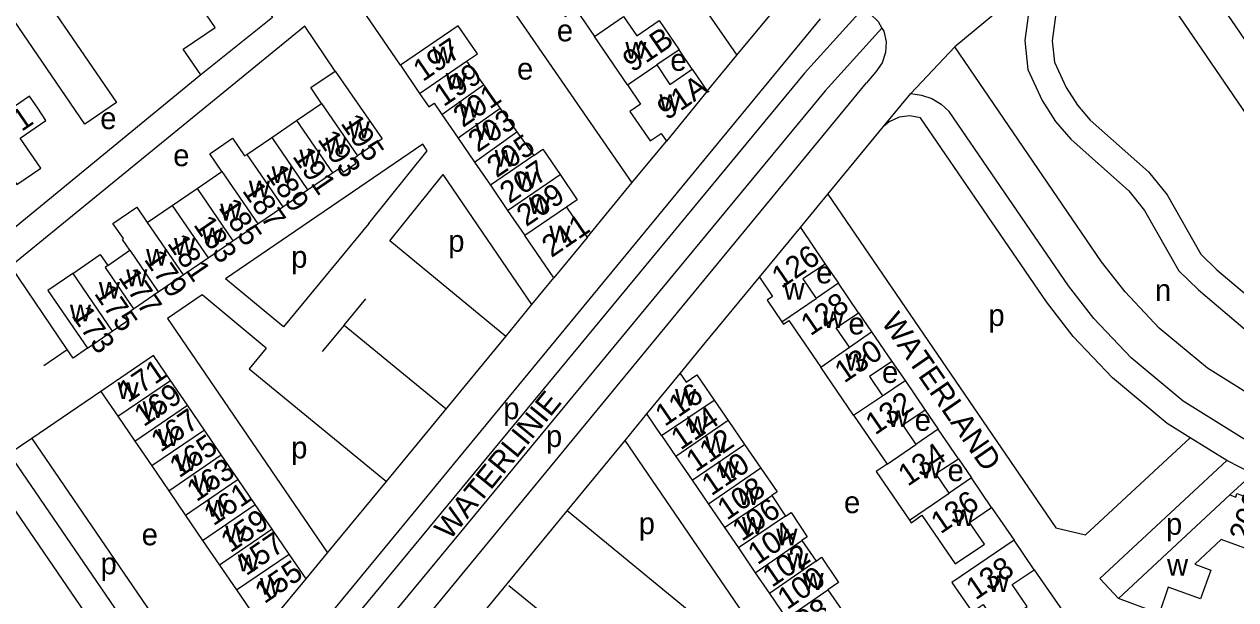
# Model space of a CAD drawing. Extents: x 154320 to 156262, y 382651 to 384180.
# Drawn here: x 155553.7 to 155775.5, y 383033.1 to 383138.5 of the extents above; entities that cross this region are included whole.
import ezdxf

# ---------------------------------------------------------------- set-up
doc = ezdxf.new("R2010")
doc.units = 0
for name, color, linetype in [('BLT_Basislijn', 7, 'Continuous'), ('BLT_Bebouwing', 7, 'Continuous'), ('BLT_Centroide', 7, 'Continuous'), ('BLT_Huisnummer', 7, 'Continuous'), ('BLT_Onderverdeling_panden', 7, 'Continuous'), ('BLT_Straatnaam', 7, 'Continuous'), ('BLT_Vlakafsluiter', 7, 'Continuous')]:
    doc.layers.add(name, color=color, linetype=linetype)

msp = doc.modelspace()

# ---------------------------------------------------------------- linework, layer by layer
at = {"layer": 'BLT_Basislijn'}
for p, q in [((155533.34, 383178.68), (155570.55, 383124.16)), ((155653.33, 383177.6), (155684.15, 383132.85)), ((155630.7, 383159.12), (155664.96, 383109.46)), ((155684.15, 383132.85), (155696.27, 383147.42)), ((155622.57, 383130.99), (155613.26, 383144.61)), ((155605.07, 383138.19), (155551.22, 383094.22)), ((155577.92, 382991.91), (155699.45, 383139.48)), ((155610.61, 383129.95), (155605.07, 383138.19)), ((155675.96, 383130.29), (155673.57, 383133.84)), ((155678.75, 383126.24), (155684.15, 383132.85)), ((155585.98, 383129.24), (155548.41, 383098.38)), ((155588.6, 382982.86), (155707.89, 383127.77)), ((155711.02, 383119.77), (155716, 383125.82)), ((155700.83, 383107.41), (155711.02, 383119.77)), ((155616.74, 383102.04), (155627.46, 383115.34)), ((155664.96, 383109.46), (155671.25, 383117.08)), ((155620.6, 383098.86), (155630.4, 383111.02)), ((155656.74, 383099.48), (155664.96, 383109.46)), ((155695.79, 383101.32), (155700.83, 383107.41)), ((155561.54, 383078.94), (155551.22, 383094.22)), ((155700.34, 383094.6), (155702.75, 383091.1)), ((155601.14, 383083.08), (155590.52, 383091.89)), ((155646.64, 383087.18), (155650.63, 383092.05)), ((155678.13, 383079.84), (155688.29, 383092.17)), ((155597.96, 383079.22), (155586.22, 383088.95)), ((155612.27, 383083.41), (155616.2, 383088.26)), ((155641.86, 383081.35), (155646.64, 383087.18)), ((155706.44, 383085.68), (155708.85, 383082.17)), ((155612.27, 383083.41), (155608.25, 383078.59)), ((155612.27, 383083.41), (155630.93, 383068.07)), ((155619.98, 383054.78), (155641.86, 383081.35)), ((155673.79, 383074.57), (155678.13, 383079.84)), ((155712.55, 383076.75), (155714.96, 383073.26)), ((155567.7, 383071.29), (155555.06, 383062.66)), ((155663.69, 383062.31), (155667.69, 383067.17)), ((155718.63, 383067.85), (155721.03, 383064.34)), ((155555.06, 383062.66), (155550.93, 383059.84)), ((155555.06, 383062.66), (155587.44, 383015.29)), ((155653.07, 383049.4), (155663.69, 383062.31)), ((155691.94, 383020.97), (155663.69, 383062.31)), ((155773.87, 383058.61), (155767.16, 383062.8)), ((155550.93, 383059.84), (155584.13, 383011.26)), ((155545.57, 383058.83), (155580.83, 383007.24)), ((155724.74, 383058.92), (155727.12, 383055.43)), ((155774.44, 383052.32), (155778.65, 383056.19)), ((155609.23, 383041.74), (155619.98, 383054.78)), ((155631.15, 383022.79), (155653.07, 383049.4)), ((155730.81, 383050.02), (155734.93, 383044.04)), ((155605.27, 383036.94), (155609.23, 383041.74)), ((155738.6, 383038.61), (155743.96, 383030.84)), ((155642.42, 383035.73), (155661.52, 383020.19)), ((155750.64, 383037.04), (155754.04, 383033.38))]:
    msp.add_line(p, q, dxfattribs=at)
for points in [[(155564.78, 383120.21), (155519.64, 383186.24)], [(155754.67, 383155.35), (155781.59, 383115.97), (155786.38, 383110.5), (155792.35, 383105.37), (155799.06, 383101.19), (155805.08, 383098.89), (155853.42, 383081.31)], [(155765.85, 383152.28), (155787.53, 383120.57), (155791.67, 383115.84), (155796.8, 383111.44), (155801.33, 383108.62)], [(155741.32, 383147.65), (155743.08, 383144.14), (155741.93, 383135.48), (155742.34, 383131.59), (155744.48, 383126.93), (155746.56, 383123.69), (155748.88, 383120.95), (155759.56, 383111.48), (155762.98, 383107.25), (155769.13, 383096.43), (155772.05, 383093.56), (155780.98, 383086.01), (155786.93, 383082.35), (155790.66, 383081.54), (155799.19, 383082.02), (155803.24, 383081.5), (155808.51, 383079.32), (155812.25, 383076.51), (155815.09, 383073.7)], [(155737.15, 383144.82), (155734.45, 383142.87), (155731.5, 383140.57), (155724.08, 383134.36)], [(155737.15, 383144.82), (155737.92, 383143.28), (155736.89, 383135.55), (155737.46, 383130.24), (155740.09, 383124.52), (155742.53, 383120.71), (155745.3, 383117.45), (155755.93, 383108.02), (155758.83, 383104.43), (155765.13, 383093.35), (155768.68, 383089.86), (155778.04, 383081.95), (155785.04, 383077.64), (155790.27, 383076.51), (155799.01, 383077), (155801.94, 383076.62), (155806.02, 383074.94), (155808.98, 383072.72), (155811.69, 383070.03), (155812.04, 383067.38), (155811.6, 383064.12), (155810.66, 383061.59), (155808.19, 383058.28)], [(155707.05, 383141.17), (155696.56, 383129.57), (155576.82, 382984.73)], [(155707.05, 383141.17), (155708.61, 383140.37), (155710.05, 383138.99), (155710.74, 383137.8)], [(155710.74, 383137.8), (155700.35, 383126.3), (155580.3, 382981.1)], [(155710.74, 383137.8), (155711.05, 383137.25), (155711.52, 383135.31), (155711.4, 383133.31), (155710.75, 383131.42), (155709.59, 383129.8), (155707.89, 383127.77)], [(155808.19, 383058.28), (155793.79, 383063.51), (155781.76, 383068.42), (155770.32, 383075.56), (155761.52, 383082.89), (155755.26, 383089.5), (155750.96, 383095.03), (155724.08, 383134.36)], [(155570.55, 383124.16), (155564.78, 383120.21)], [(155716, 383125.82), (155717.98, 383125.54), (155719.87, 383124.89), (155721.59, 383123.87), (155723.07, 383122.55)], [(155805.3, 383051.35), (155791.1, 383056.52), (155778.33, 383061.72), (155765.92, 383069.47), (155756.38, 383077.4), (155749.56, 383084.61), (155744.9, 383090.61), (155723.07, 383122.55)], [(155717.81, 383121.38), (155715.84, 383121.76), (155713.86, 383121.51), (155712.05, 383120.66), (155711.02, 383119.77)], [(155767.16, 383062.8), (155762.98, 383065.41), (155752.95, 383073.75), (155745.76, 383081.35), (155740.86, 383087.66), (155717.81, 383121.38)], [(155627.46, 383115.34), (155626.65, 383116.53), (155590.52, 383091.89)], [(155646.64, 383087.18), (155630.4, 383111.02)], [(155700.83, 383107.41), (155742.55, 383046.3), (155748.01, 383045.04), (155767.16, 383062.8)], [(155616.74, 383102.04), (155601.14, 383083.08)], [(155641.86, 383081.35), (155620.6, 383098.86)], [(155586.22, 383088.95), (155579.92, 383084.66), (155609.23, 383041.74)], [(155557.28, 383076.03), (155561.54, 383078.94)], [(155565.23, 383079.17), (155562.6, 383077.39), (155561.54, 383078.94)], [(155597.96, 383079.22), (155594.85, 383075.43), (155619.98, 383054.78)], [(155778.65, 383056.19), (155773.87, 383058.61)], [(155678.17, 383028.75), (155653.07, 383049.4)]]:
    msp.add_lwpolyline(points, dxfattribs=at)
at = {"layer": 'BLT_Bebouwing'}
for p, q in [((155599.13, 383139.76), (155585.98, 383129.24)), ((155669.92, 383139.21), (155673.57, 383133.84)), ((155664.12, 383127.42), (155658.09, 383136.29)), ((155673.57, 383133.84), (155669.48, 383131.06)), ((155675.96, 383130.29), (155678.75, 383126.24)), ((155637.75, 383127.42), (155640.82, 383123.1)), ((155678.75, 383126.24), (155671.25, 383117.08)), ((155603.54, 383120.91), (155608.09, 383124.02)), ((155630.15, 383122), (155633.14, 383117.63)), ((155640.82, 383123.1), (155643.89, 383118.79)), ((155598.98, 383117.8), (155603.54, 383120.91)), ((155594.42, 383114.68), (155598.98, 383117.8)), ((155633.14, 383117.63), (155636.13, 383113.26)), ((155643.89, 383118.79), (155646.96, 383114.47)), ((155636.13, 383113.26), (155639.02, 383109.03)), ((155605.55, 383108.18), (155610.11, 383111.29)), ((155639.02, 383109.03), (155642.18, 383104.4)), ((155580.76, 383105.35), (155585.31, 383108.46)), ((155601, 383105.06), (155605.55, 383108.18)), ((155576.2, 383102.24), (155580.76, 383105.35)), ((155596.44, 383101.95), (155601, 383105.06)), ((155642.18, 383104.4), (155645.33, 383099.8)), ((155652.95, 383105), (155656.74, 383099.48)), ((155591.89, 383098.84), (155596.44, 383101.95)), ((155650.63, 383092.05), (155645.33, 383099.8)), ((155688.29, 383092.17), (155695.79, 383101.32)), ((155587.33, 383095.72), (155591.89, 383098.84)), ((155656.74, 383099.48), (155650.63, 383092.05)), ((155568.95, 383094.33), (155573.02, 383097.12)), ((155582.78, 383092.61), (155587.33, 383095.72)), ((155578.22, 383089.5), (155582.78, 383092.61)), ((155573.67, 383086.38), (155578.22, 383089.5)), ((155705.55, 383066.9), (155699.52, 383075.73)), ((155583.54, 383068.75), (155580.44, 383073.3)), ((155667.69, 383067.17), (155673.79, 383074.57)), ((155586.65, 383064.21), (155583.54, 383068.75)), ((155679.99, 383069.69), (155682.57, 383065.93)), ((155570.81, 383066.72), (155573.9, 383062.17)), ((155670.39, 383063.21), (155667.69, 383067.17)), ((155705.55, 383066.9), (155711.67, 383057.94)), ((155589.75, 383059.67), (155586.65, 383064.21)), ((155573.9, 383062.17), (155577.01, 383057.63)), ((155670.39, 383063.21), (155673.01, 383059.36)), ((155685.56, 383061.58), (155688.55, 383057.23)), ((155577.01, 383057.63), (155580.12, 383053.09)), ((155592.85, 383055.12), (155589.75, 383059.67)), ((155673.01, 383059.36), (155675.99, 383055)), ((155750.64, 383037.04), (155773.87, 383058.61)), ((155580.12, 383053.09), (155583.22, 383048.55)), ((155595.96, 383050.58), (155592.85, 383055.12)), ((155675.99, 383055), (155678.97, 383050.64)), ((155690.54, 383052.2), (155693.1, 383048.41)), ((155754.04, 383033.38), (155774.44, 383052.32)), ((155599.06, 383046.03), (155595.96, 383050.58)), ((155678.97, 383050.64), (155681.9, 383046.35)), ((155583.22, 383048.55), (155586.33, 383044)), ((155602.16, 383041.49), (155599.06, 383046.03)), ((155681.9, 383046.35), (155684.45, 383042.61)), ((155586.33, 383044), (155589.44, 383039.46)), ((155684.45, 383042.61), (155687.54, 383038.08)), ((155696.07, 383043.99), (155698.68, 383040.22)), ((155605.27, 383036.94), (155602.16, 383041.49)), ((155589.44, 383039.46), (155592.54, 383034.92)), ((155687.54, 383038.08), (155690.12, 383034.3)), ((155599.14, 383029.51), (155605.27, 383036.94)), ((155690.12, 383034.3), (155693.27, 383029.7)), ((155700.81, 383034.93), (155703.43, 383031.15)), ((155760.94, 383030.78), (155754.04, 383033.38))]:
    msp.add_line(p, q, dxfattribs=at)
for points in [[(155585.98, 383129.24), (155582.75, 383133.96), (155588.63, 383137.9), (155585.36, 383142.77), (155594.27, 383148.74), (155597.6, 383143.82), (155596.39, 383143), (155597.78, 383140.94), (155598.14, 383141.18), (155599.13, 383139.76)], [(155650.94, 383144.76), (155649.96, 383143.94), (155652.71, 383139.96), (155654.69, 383141.3), (155658.09, 383136.29)], [(155663.41, 383139.96), (155665.82, 383136.42), (155669.92, 383139.21)], [(155634.68, 383131.73), (155636.68, 383133.09), (155633.15, 383138.24), (155622.57, 383130.99)], [(155622.57, 383130.99), (155626.06, 383125.86)], [(155634.68, 383131.73), (155634.68, 383131.73), (155637.75, 383127.42)], [(155669.48, 383131.06), (155671.9, 383127.5), (155675.96, 383130.29)], [(155608.09, 383124.02), (155606.12, 383126.91), (155610.61, 383129.95)], [(155610.61, 383129.95), (155619.22, 383117.52), (155614.67, 383114.41)], [(155664.12, 383127.42), (155666.54, 383123.85), (155664.56, 383122.53), (155668.29, 383117.18), (155670.28, 383118.5), (155671.25, 383117.08)], [(155626.06, 383125.86), (155627.73, 383123.4), (155628.75, 383124.05), (155630.15, 383122)], [(155589.87, 383111.57), (155587.66, 383114.78), (155591.83, 383117.63), (155594.03, 383114.41), (155594.42, 383114.68)], [(155646.96, 383114.47), (155648.61, 383115.61), (155651.78, 383110.98)], [(155610.11, 383111.29), (155611.49, 383112.23), (155612.04, 383111.42), (155614.48, 383113.09), (155613.93, 383113.9), (155614.67, 383114.41)], [(155585.31, 383108.46), (155585.31, 383108.46), (155589.87, 383111.57)], [(155651.78, 383110.98), (155654.95, 383106.36), (155652.95, 383105)], [(155573.02, 383097.12), (155571.63, 383099.12), (155571.82, 383099.25), (155569.91, 383102.05), (155574.29, 383105.04), (155576.2, 383102.24)], [(155695.79, 383101.32), (155700.34, 383094.6)], [(155562.54, 383092.89), (155567.59, 383096.33), (155568.95, 383094.33)], [(155700.34, 383094.6), (155696.24, 383091.87), (155698.67, 383088.31)], [(155562.54, 383092.89), (155557.99, 383089.78), (155565.23, 383079.17)], [(155688.29, 383092.17), (155690.69, 383088.64), (155689.69, 383087.98), (155692.39, 383084.03)], [(155702.75, 383091.1), (155698.67, 383088.31)], [(155706.44, 383085.68), (155702.75, 383091.1)], [(155569.78, 383082.29), (155572.85, 383084.4), (155572.18, 383085.37), (155573.67, 383086.38)], [(155692.39, 383084.03), (155692.7, 383083.58), (155693.69, 383084.26), (155699.52, 383075.73)], [(155704.78, 383079.36), (155702.32, 383082.93), (155706.44, 383085.68)], [(155565.23, 383079.17), (155569.78, 383082.29)], [(155704.78, 383079.36), (155708.85, 383082.17)], [(155708.85, 383082.17), (155712.55, 383076.75)], [(155580.44, 383073.3), (155577.33, 383077.84), (155567.7, 383071.29)], [(155712.55, 383076.75), (155708.45, 383074.03), (155710.85, 383070.48)], [(155673.79, 383074.57), (155674.86, 383073), (155676.83, 383074.33), (155679.99, 383069.69)], [(155710.85, 383070.48), (155714.96, 383073.26)], [(155714.96, 383073.26), (155718.63, 383067.85)], [(155567.7, 383071.29), (155570.81, 383066.72)], [(155718.63, 383067.85), (155714.54, 383065.11), (155716.95, 383061.57)], [(155682.57, 383065.93), (155685.56, 383061.58)], [(155721.03, 383064.34), (155716.95, 383061.57)], [(155724.74, 383058.92), (155721.03, 383064.34)], [(155711.67, 383057.94), (155709.68, 383056.59), (155715.75, 383047.71)], [(155723.04, 383052.66), (155720.62, 383056.22), (155724.74, 383058.92)], [(155688.55, 383057.23), (155691.54, 383052.88), (155690.54, 383052.2)], [(155727.12, 383055.43), (155723.04, 383052.66)], [(155730.81, 383050.02), (155727.12, 383055.43)], [(155774.44, 383052.32), (155775.51, 383051.94), (155775.73, 383052.56), (155779.55, 383051.2), (155779.33, 383050.58), (155782.02, 383049.63), (155779.23, 383041.84), (155772.84, 383044.18), (155768.05, 383039.66), (155770.99, 383038.54), (155769.07, 383033.27), (155763.16, 383035.43), (155761.49, 383030.57)], [(155693.1, 383048.41), (155694.09, 383049.08), (155697.06, 383044.67), (155696.07, 383043.99)], [(155715.75, 383047.71), (155716.07, 383047.24), (155718.05, 383048.59), (155724.14, 383039.68), (155729.52, 383043.31), (155726.78, 383047.27), (155730.81, 383050.02)], [(155734.93, 383044.04), (155723.56, 383036.29), (155723.56, 383036.29), (155727.26, 383030.9), (155729.24, 383032.26), (155731.96, 383028.25), (155737.31, 383031.92), (155734.59, 383035.9), (155738.6, 383038.61)], [(155738.6, 383038.61), (155734.93, 383044.04)], [(155698.68, 383040.22), (155699.68, 383040.91), (155702.79, 383036.3), (155700.81, 383034.93)], [(155592.54, 383034.92), (155596.07, 383029.75), (155598.07, 383031.12), (155599.14, 383029.51)]]:
    msp.add_lwpolyline(points, dxfattribs=at)
msp.add_lwpolyline([(155552.95, 383117.67), (155557.65, 383120.9), (155556.13, 383123.12), (155554.62, 383125.32), (155545.56, 383119.11), (155552.32, 383109.16), (155556.73, 383112.14)], close=True, dxfattribs=at)
at = {"layer": 'BLT_Onderverdeling_panden'}
for p, q in [((155658.09, 383136.29), (155663.41, 383139.96)), ((155626.06, 383125.86), (155634.68, 383131.73)), ((155664.12, 383127.42), (155669.48, 383131.06)), ((155630.15, 383122), (155637.75, 383127.42)), ((155640.82, 383123.1), (155633.14, 383117.63)), ((155603.54, 383120.91), (155610.11, 383111.29)), ((155598.98, 383117.8), (155605.55, 383108.18)), ((155636.13, 383113.26), (155643.89, 383118.79)), ((155594.42, 383114.68), (155601, 383105.06)), ((155646.96, 383114.47), (155639.02, 383109.03)), ((155589.87, 383111.57), (155596.44, 383101.95)), ((155642.18, 383104.4), (155651.78, 383110.98)), ((155585.31, 383108.46), (155591.89, 383098.84)), ((155580.76, 383105.35), (155587.33, 383095.72)), ((155652.95, 383105), (155645.33, 383099.8)), ((155576.2, 383102.24), (155582.78, 383092.61)), ((155573.02, 383097.12), (155578.22, 383089.5)), ((155562.54, 383092.89), (155569.78, 383082.29)), ((155692.39, 383084.03), (155698.67, 383088.31)), ((155699.52, 383075.73), (155704.78, 383079.36)), ((155570.81, 383066.72), (155580.44, 383073.3)), ((155573.9, 383062.17), (155583.54, 383068.75)), ((155670.39, 383063.21), (155679.99, 383069.69)), ((155705.55, 383066.9), (155710.85, 383070.48)), ((155586.65, 383064.21), (155577.01, 383057.63)), ((155682.57, 383065.93), (155673.01, 383059.36)), ((155675.99, 383055), (155685.56, 383061.58)), ((155711.67, 383057.94), (155716.95, 383061.57)), ((155580.12, 383053.09), (155589.75, 383059.67)), ((155688.55, 383057.23), (155678.97, 383050.64)), ((155592.85, 383055.12), (155583.22, 383048.55)), ((155681.9, 383046.35), (155690.54, 383052.2)), ((155715.75, 383047.71), (155723.04, 383052.66)), ((155586.33, 383044), (155595.96, 383050.58)), ((155693.1, 383048.41), (155684.45, 383042.61)), ((155687.54, 383038.08), (155696.07, 383043.99)), ((155592.54, 383034.92), (155602.16, 383041.49)), ((155698.68, 383040.22), (155690.12, 383034.3)), ((155693.27, 383029.7), (155700.81, 383034.93))]:
    msp.add_line(p, q, dxfattribs=at)
for points in [[(155608.09, 383124.02), (155614.67, 383114.41), (155614.67, 383114.41)], [(155568.95, 383094.33), (155568.46, 383094), (155573.67, 383086.38)], [(155599.06, 383046.03), (155599.06, 383046.03), (155589.44, 383039.46)]]:
    msp.add_lwpolyline(points, dxfattribs=at)
at = {"layer": 'BLT_Vlakafsluiter'}
msp.add_line((155716, 383125.82), (155724.08, 383134.36), dxfattribs=at)

# ---------------------------------------------------------------- texts
at = {"layer": 'BLT_Centroide'}
for s, p in [('e', (155651.2, 383135.38)), ('w', (155663.75, 383132.2)), ('w', (155628.44, 383131.33)), ('e', (155671.99, 383129.99)), ('e', (155643.91, 383128.38)), ('w', (155630.84, 383126.53)), ('w', (155633.24, 383121.41)), ('w', (155669.99, 383122.6)), ('e', (155567.58, 383119.31)), ('w', (155613.07, 383117.65)), ('w', (155636.26, 383117.34)), ('w', (155608.78, 383114.67)), ('e', (155580.95, 383112.52)), ('w', (155604.07, 383112.46)), ('w', (155639.81, 383112.43)), ('w', (155598.97, 383109.43)), ('w', (155643.77, 383108.46)), ('w', (155594.8, 383106.8)), ('w', (155646.07, 383103.76)), ('w', (155589.55, 383102.57)), ('w', (155586.17, 383098.18)), ('p', (155631.32, 383096.84)), ('w', (155649.82, 383098.54)), ('w', (155581.1, 383096.27)), ('w', (155575.98, 383094.3)), ('p', (155602.55, 383093.92)), ('w', (155572.34, 383090.54)), ('e', (155698.67, 383091.06)), ('w', (155567.33, 383088.27)), ('w', (155692.72, 383088.08)), ('n', (155760.73, 383087.83)), ('w', (155562.03, 383084.1)), ('p', (155730.23, 383083.26)), ('w', (155699.93, 383082.89)), ('e', (155704.59, 383081.72)), ('w', (155704.04, 383075.1)), ('e', (155710.74, 383072.83)), ('w', (155570.75, 383069.86)), ('w', (155672.84, 383068.66)), ('w', (155575.34, 383066.42)), ('p', (155641.39, 383066.18)), ('w', (155675.03, 383063.65)), ('w', (155711.76, 383064.74)), ('e', (155716.72, 383064.06)), ('w', (155578.16, 383061.3)), ('p', (155649.21, 383061.1)), ('p', (155602.55, 383059.01)), ('w', (155678.37, 383059.99)), ('w', (155581.39, 383056.7)), ('w', (155680.67, 383055.4)), ('w', (155717.76, 383055.36)), ('e', (155722.75, 383054.84)), ('w', (155584.63, 383052.84)), ('w', (155684.42, 383050.49)), ('w', (155587.13, 383048.35)), ('e', (155703.78, 383048.99)), ('w', (155723.77, 383046.63)), ('w', (155590.47, 383043.65)), ('p', (155666.19, 383045.13)), ('w', (155685.11, 383045.19)), ('p', (155762.75, 383045.02)), ('e', (155575.17, 383043.1)), ('w', (155691.39, 383043.07)), ('p', (155567.64, 383037.79)), ('w', (155592.77, 383038.32)), ('w', (155693.37, 383038.58)), ('w', (155762.94, 383037.53)), ('w', (155696.18, 383034.93)), ('w', (155730.16, 383034.52)), ('w', (155596.84, 383034.04))]:
    msp.add_text(s, height=4, dxfattribs=at).set_placement(p)
at = {"layer": 'BLT_Huisnummer'}
for s, rotation, p in [('91B', 34.3538, (155665.03, 383129.6)), ('197', 34.3538, (155626.65, 383127.9)), ('199', 34.3538, (155630.47, 383123.31)), ('91A', 34.3538, (155671.35, 383120.84)), ('201', 34.3538, (155633.99, 383119.5)), ('1', 34.3538, (155553.18, 383118.76)), ('195', 304.3538, (155611.49, 383120.38)), ('203', 34.3538, (155636.72, 383114.95)), ('193', 304.3538, (155607.26, 383117.42)), ('205', 34.3538, (155640.16, 383110.29)), ('191', 304.3538, (155602.67, 383114.32)), ('207', 34.3538, (155642.51, 383105.53)), ('189', 304.3538, (155597.79, 383111.13)), ('187', 304.3538, (155593.48, 383108.01)), ('209', 34.3538, (155645.6, 383101.34)), ('185', 304.3538, (155589.13, 383104.92)), ('183', 304.3538, (155584.55, 383101.79)), ('211', 34.3538, (155650.22, 383095.68)), ('181', 304.3538, (155579.73, 383098.4)), ('126', 34.3538, (155692.32, 383090.04)), ('179', 304.3538, (155575.5, 383095.46)), ('177', 304.3538, (155570.79, 383092.15)), ('175', 304.3538, (155566.36, 383089.21)), ('128', 34.3538, (155697.64, 383081.33)), ('173', 304.3538, (155562.18, 383085.23)), ('130', 34.3538, (155703.83, 383072.7)), ('171', 34.3538, (155572.66, 383069.09)), ('169', 34.3538, (155575.54, 383064.69)), ('116', 34.3538, (155670.97, 383064.76)), ('132', 34.3538, (155709.48, 383063.18)), ('167', 34.3538, (155578.63, 383060.03)), ('114', 34.3538, (155673.86, 383060.44)), ('112', 34.3538, (155676.62, 383056.39)), ('165', 34.3538, (155582.03, 383055.33)), ('110', 34.3538, (155679.48, 383052.04)), ('134', 34.3538, (155715.46, 383053.79)), ('163', 34.3538, (155585.2, 383050.96)), ('108', 34.3538, (155682.35, 383047.57)), ('161', 34.3538, (155588.3, 383046.54)), ('136', 34.3538, (155721.47, 383045.06)), ('106', 34.3538, (155685.08, 383043.71)), ('206', 70.0188, (155777.93, 383043.48)), ('159', 34.3538, (155591.42, 383041.62)), ('104', 34.3538, (155687.94, 383039.41)), ('157', 34.3538, (155594.31, 383037.4)), ('102', 34.3538, (155690.58, 383035.28)), ('155', 34.3538, (155597.65, 383032.3)), ('138', 34.3538, (155727.88, 383032.96)), ('100', 34.3538, (155693.36, 383031.19)), ('98', 34.3538, (155696.75, 383027.05))]:
    msp.add_text(s, height=4, rotation=rotation, dxfattribs=at).set_placement(p)
at = {"layer": 'BLT_Straatnaam'}
for s, rotation, p in [('WATERLAND', 304.5737, (155710.49, 383083.96)), ('WATERLINIE', 50.8558, (155631.59, 383043.88))]:
    msp.add_text(s, height=4, rotation=rotation, dxfattribs=at).set_placement(p)

doc.saveas('drawing.dxf')
